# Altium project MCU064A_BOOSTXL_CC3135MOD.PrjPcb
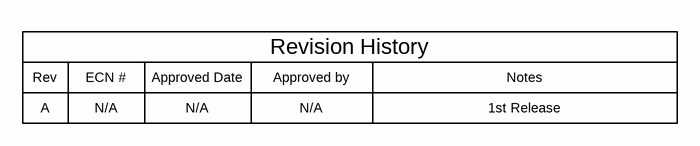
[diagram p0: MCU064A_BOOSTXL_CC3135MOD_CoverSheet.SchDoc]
CopyrightYear: 2016; EVM_Orderable: BOOSTXL-CC3135MOD; PCB_Layout: PMovva; PCB_Rev: A; PRJ_Customer: Public Release; PRJ_Engineer: PMovva; PRJ_Number: MCU064; PRJ_Title: BOOSTXL-CC3135MOD; SCH_Rev: A; TechSupport: http://www.ti.com/support; TID: N/A
4 sheets, 113 parts. Net scope: global (net labels, ports and power ports of the same name join across sheets).
Board file: MCU064A_BOOSTXL_CC3135MOD_PCB.PcbDoc
Sheets:
  MCU064A_BOOSTXL_CC3135MOD_CoverSheet.SchDoc
  MCU064A_BOOSTXL_CC3135MOD_Engine.SchDoc
  MCU064A_BOOSTXL_CC3135MOD_EVMHardware.SchDoc
  MCU064A_BOOSTXL_CC3135MOD_HostInterface.SchDoc

## Sheet MCU064A_BOOSTXL_CC3135MOD_CoverSheet.SchDoc: Cover
size 431 x 279 mm; Date: Not shown in title block; ApprovedBy: Not shown in title block; CheckedBy: Not shown in title block; Author: Not shown in title block; CompanyName: Not shown in title block; DrawnBy: PMovva; Engineer: Not shown in title block; Organization: Not shown in title block; Address1: Not shown in title block; Address2: Not shown in title block; Address3: Not shown in title block; Address4: Not shown in title block; DocumentNumber: 1; Revision: Use project parameter SCH_Rev; SheetNumber: 1; SheetTotal: 4; PageSetup: Record=PageOptions¦CenterHorizontal=True¦CenterVertical=True¦PrintScale=1.00¦XCorrection=1.00¦YCorrection=1.00¦PrintKind=0¦BorderSize=5000000¦LeftOffset=0¦BottomOffset=0¦Orientation=2¦PaperLength=1000¦PaperWidth=1000¦Scale=100¦PaperSource=15¦PrintQuality=600¦MediaType=1¦DitherType=10¦PaperKind=Letter¦PrintScaleMode=1

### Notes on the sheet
- Rev
- A
- ECN #
- N/A
- Approved Date
- Approved by
- Revision History
- Notes
- 1st Release

## Sheet MCU064A_BOOSTXL_CC3135MOD_Engine.SchDoc: Engine Area
size 558 x 431 mm; Date: Not shown in title block; ApprovedBy: Not shown in title block; CheckedBy: Not shown in title block; Author: Not shown in title block; CompanyName: Not shown in title block; DrawnBy: PMovva; Engineer: Not shown in title block; Organization: Not shown in title block; Address1: Not shown in title block; Address2: Not shown in title block; Address3: Not shown in title block; Address4: Not shown in title block; DocumentNumber: 2; Revision: Use project parameter SCH_Rev; SheetNumber: 2; SheetTotal: 4; PageSetup: Record=PageOptions¦CenterHorizontal=True¦CenterVertical=True¦PrintScale=1.00¦XCorrection=1.00¦YCorrection=1.00¦PrintKind=0¦BorderSize=5000000¦LeftOffset=0¦BottomOffset=0¦Orientation=2¦PaperLength=1000¦PaperWidth=1000¦Scale=100¦PaperSource=15¦PrintQuality=600¦MediaType=1¦DitherType=10¦PaperKind=Letter¦PrintScaleMode=1
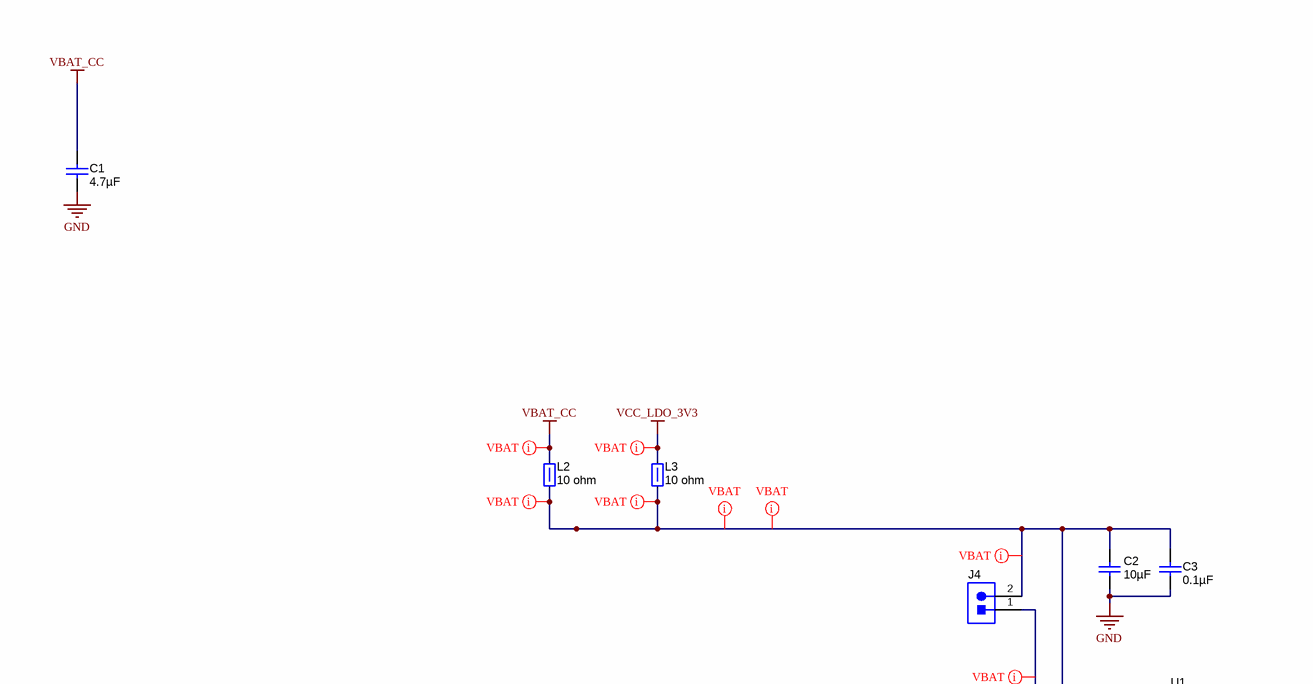
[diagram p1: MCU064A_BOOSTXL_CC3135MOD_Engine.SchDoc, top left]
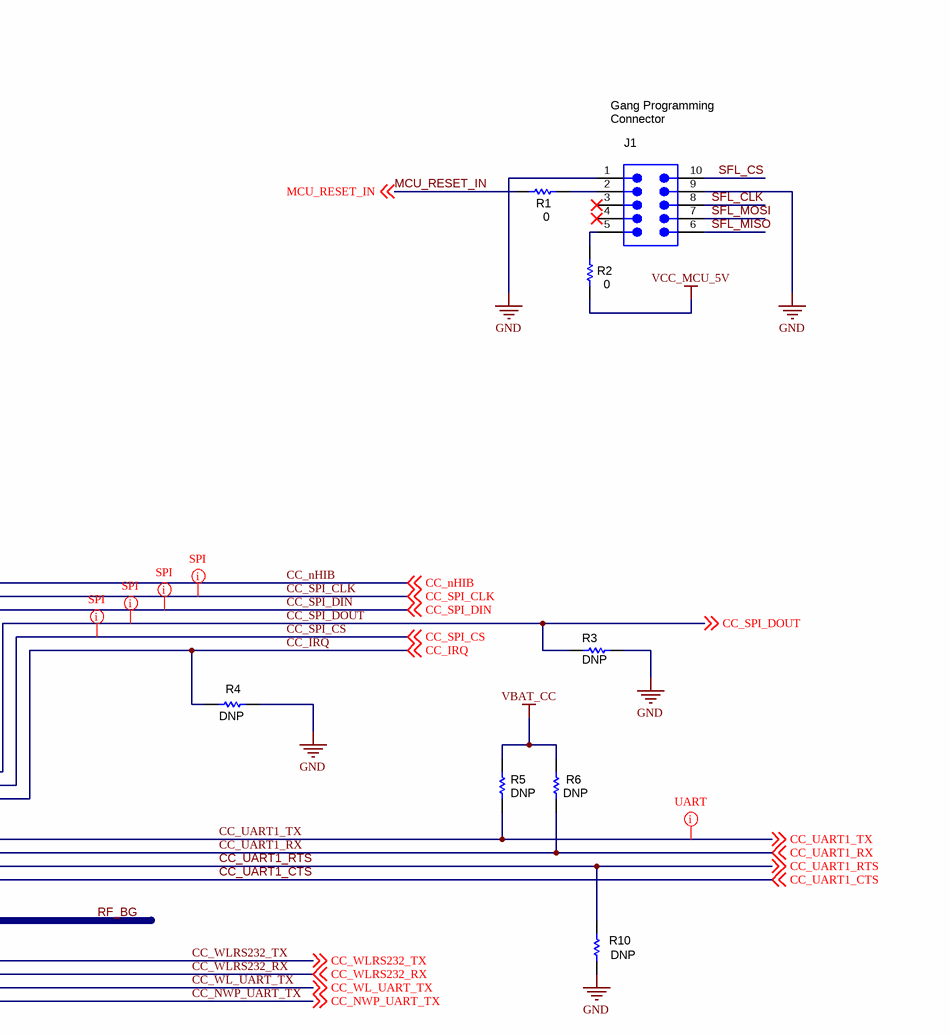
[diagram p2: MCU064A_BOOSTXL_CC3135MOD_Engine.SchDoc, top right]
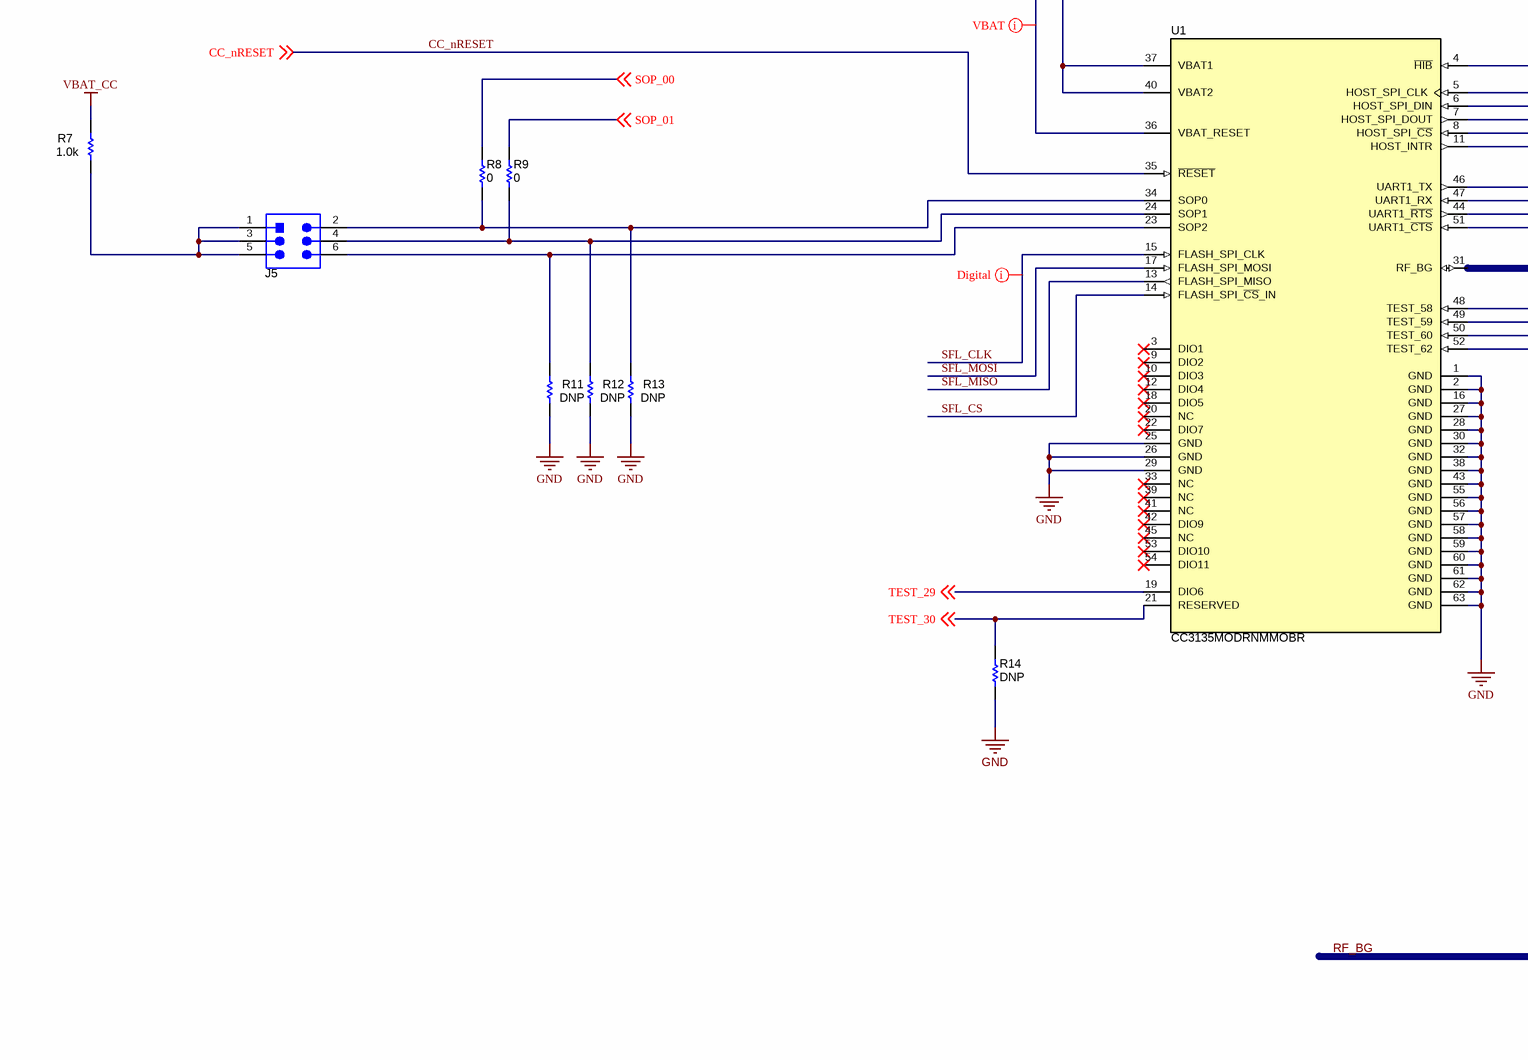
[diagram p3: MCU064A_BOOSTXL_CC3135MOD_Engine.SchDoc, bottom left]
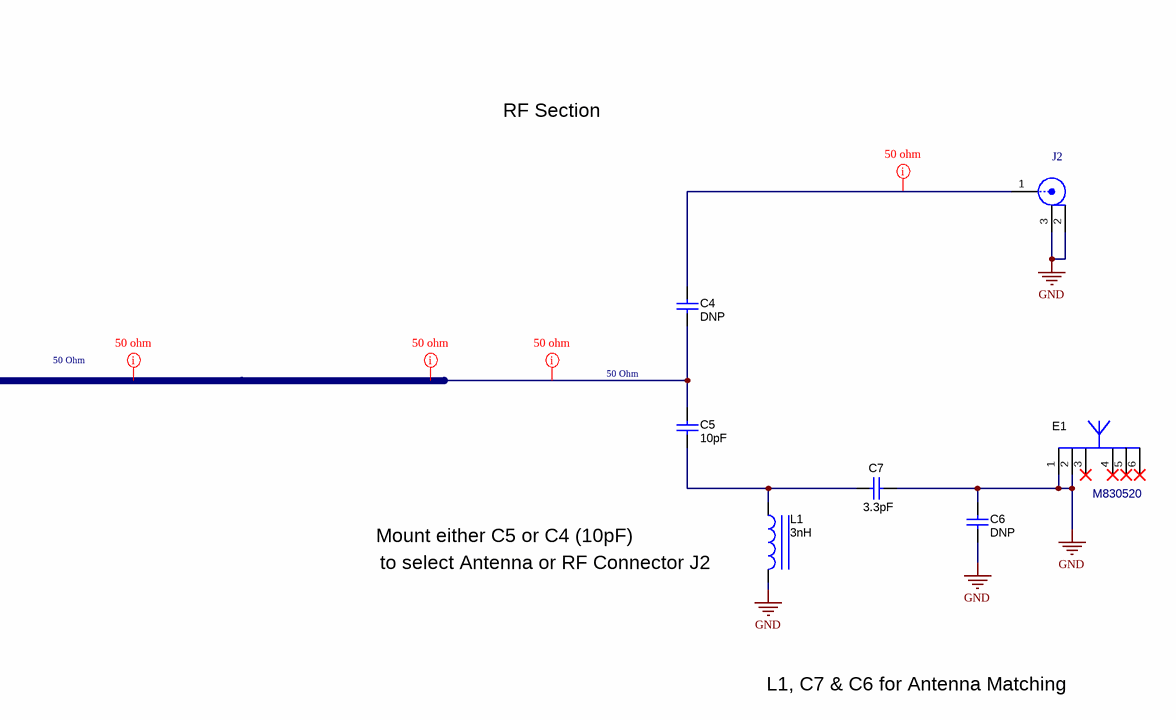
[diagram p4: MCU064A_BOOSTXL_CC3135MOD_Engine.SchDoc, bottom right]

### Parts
C1  ValueDisplayed: 4.7µF  [0402]  (hidden comment: GRM155R60J475ME47D)
C2  ValueDisplayed: 10µF  [0603]  (hidden comment: GRM188R60J106ME47D)
C3  ValueDisplayed: 0.1µF  [0402]  (hidden comment: GRM155R60J104KA01D)
C4  ValueDisplayed: DNP  [0402]  (hidden comment: 500R07S100JV4T)
C5  ValueDisplayed: 10pF  [0402]  (hidden comment: 500R07S100JV4T)
C6  ValueDisplayed: DNP  [0402]  (hidden comment: GRM1555C1H1R8CA01D)
C7  ValueDisplayed: 3.3pF  [0402]  (hidden comment: GJM1555C1H3R3BB01D)
E1  M830520  [Ethertronics_M830520]
J1  TC2050-IDC-430-FP  [Tag_TC2050-NL]  (value not drawn)  (no BOM)
J2  U.FL-R-SMT-1  [CONN_UFL-R-SMT-1]  (value not drawn)
J4  961102-6404-AR  [3M_961102-6404-AR]  (value not drawn)
J5  GRPB032VWVN-RC  [Sullins_GRPB032VWVN-RC]  (value not drawn)
L1  ValueDisplayed: 3nH  [IND_LQG15H]  (hidden comment: LQG15HS3N0S02D)
L2  value 10 ohm  [0402]  (hidden comment: BLM15AX100SN1D)
L3  value 10 ohm  [0402]  (hidden comment: BLM15AX100SN1D)
R1  ValueDisplayed: 0  [0402]  (hidden comment: ERJ-2GE0R00X)
R2  ValueDisplayed: 0  [0402]  (hidden comment: ERJ-2GE0R00X)
R3  ValueDisplayed: DNP  [0402]  (hidden comment: CRCW0402100KJNED)
R4  ValueDisplayed: DNP  [0402]  (hidden comment: CRCW0402100KJNED)
R5  ValueDisplayed: DNP  [0402]  (hidden comment: CRCW0402100KJNED)
R6  ValueDisplayed: DNP  [0402]  (hidden comment: CRCW0402100KJNED)
R7  ValueDisplayed: 1.0k  [0402]  (hidden comment: CRCW04021K00JNED)
R8  ValueDisplayed: 0  [0402]  (hidden comment: ERJ-2GE0R00X)
R9  ValueDisplayed: 0  [0402]  (hidden comment: ERJ-2GE0R00X)
R10  ValueDisplayed: DNP  [0402]  (hidden comment: CRCW0402100KJNED)
R11  ValueDisplayed: DNP  [0402]  (hidden comment: CRCW0402100KJNED)
R12  ValueDisplayed: DNP  [0402]  (hidden comment: CRCW0402100KJNED)
R13  ValueDisplayed: DNP  [0402]  (hidden comment: CRCW0402100KJNED)
R14  ValueDisplayed: DNP  [0402]  (hidden comment: CRCW0402100KJNED)
U1  CC3135MODRNMMOBR  [MOB0063A]

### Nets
GND: C1.2 C2.2 C3.2 C6.1 C6.2 C7.1 E1.1(Feed) E1.2(GND) J1.1 J1.9 J2.2 J2.3 L1.2 R3.2 R4.2 R10.2 R11.2 R12.2 R13.2 R14.1 U1.1(GND) U1.2(GND) U1.16(GND) U1.25(GND) U1.26(GND) U1.27(GND) U1.28(GND) U1.29(GND) U1.30(GND) U1.32(GND) U1.38(GND) U1.43(GND) U1.55(GND) U1.56(GND) U1.57(GND) U1.58(GND) U1.59(GND) U1.60(GND) U1.61(GND) U1.62(GND) U1.63(GND)
VBAT_CC: C1.1 L2.2 R5.1 R6.1 R7.1
VCC_LDO_3V3: L3.2
VCC_MCU_5V: R2.1
CC_IRQ: R4.1 U1.11(HOST_INTR) ; off-sheet CC_IRQ
CC_nHIB: U1.4(~{HIB}) ; off-sheet CC_nHIB
CC_nRESET: U1.35(~{RESET}) ; off-sheet CC_nRESET
CC_NWP_UART_TX: U1.52(TEST_62) ; off-sheet CC_NWP_UART_TX
CC_SPI_CLK: U1.5(HOST_SPI_CLK) ; off-sheet CC_SPI_CLK
CC_SPI_CS: U1.8(HOST_SPI_~{CS}) ; off-sheet CC_SPI_CS
CC_SPI_DIN: U1.6(HOST_SPI_DIN) ; off-sheet CC_SPI_DIN
CC_SPI_DOUT: R3.1 U1.7(HOST_SPI_DOUT) ; off-sheet CC_SPI_DOUT
CC_UART1_CTS: U1.51(UART1_~{CTS}) ; off-sheet CC_UART1_CTS
CC_UART1_RTS: R10.1 U1.44(UART1_~{RTS}) ; off-sheet CC_UART1_RTS
CC_UART1_RX: R6.2 U1.47(UART1_RX) ; off-sheet CC_UART1_RX
CC_UART1_TX: R5.2 U1.46(UART1_TX) ; off-sheet CC_UART1_TX
CC_WL_UART_TX: U1.50(TEST_60) ; off-sheet CC_WL_UART_TX
CC_WLRS232_RX: U1.49(TEST_59) ; off-sheet CC_WLRS232_RX
CC_WLRS232_TX: U1.48(TEST_58) ; off-sheet CC_WLRS232_TX
MCU_RESET_IN: R1.2 ; off-sheet MCU_RESET_IN
RF_BG: C4.2 C5.1 U1.31(RF_BG)
SFL_CLK: J1.8 U1.15(FLASH_SPI_CLK)
SFL_CS: J1.10 U1.14(FLASH_SPI_~{CS}_IN)
SFL_MISO: J1.6 U1.13(FLASH_SPI_MISO)
SFL_MOSI: J1.7 U1.17(FLASH_SPI_MOSI)
SOP_00: R8.2 ; off-sheet SOP_00
SOP_01: R9.2 ; off-sheet SOP_01
TEST_29: U1.19(DIO6) ; off-sheet TEST_29
TEST_30: R14.2 U1.21(RESERVED) ; off-sheet TEST_30
NetC2_1: C2.1 C3.1 J4.2 L2.1 L3.1 U1.37(VBAT1) U1.40(VBAT2)
NetC4_1: C4.1 J2.1
NetC5_2: C5.2 C7.2 L1.1
NetJ1_2: J1.2 R1.1
NetJ1_5: J1.5 R2.2
NetJ4_1: J4.1 U1.36(VBAT_RESET)
NetJ5_1: J5.1 J5.3 J5.5 R7.2
NetJ5_2: J5.2 R8.1 R13.1 U1.34(SOP0)
NetJ5_4: J5.4 R9.1 R12.1 U1.24(SOP1)
NetJ5_6: J5.6 R11.1 U1.23(SOP2)

Not connected (* = marked no-connect by the designer): E1 3(GND)* 4(Feed)* 5* 6*; J1 3* 4*; U1 3(DIO1)* 9(DIO2)* 10(DIO3)* 12(DIO4)* 18(DIO5)* 20(NC)* 22(DIO7)* 33(NC)* 39(NC)* 41(NC)* 42(DIO9)* 45(NC)* 53(DIO10)* 54(DIO11)*

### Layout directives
net class 50 ohm: NetC4_1, RF_BG
net class Undefined: CC_SPI_CLK, CC_SPI_CS, CC_SPI_DIN, CC_SPI_DOUT, CC_UART1_TX, NetC2_1, NetJ4_1, SFL_CLK, VBAT_CC, VCC_LDO_3V3
rule Undefined: NetC2_1

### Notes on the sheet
- Gang Programming
  Connector
- RF Section
- 50 Ohm
- Mount either C5 or C4 (10pF)
- (near L1) to select Antenna or RF Connector J2
- L1, C7 & C6 for Antenna Matching

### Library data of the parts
C1 = GRM155R60J475ME47D: CAP, CERM, 4.7 µF, 6.3 V, +/- 20%, X5R, 0402; Manufacturer: MuRata; Polarized: N; CompType: Capacitor; Value: 4.7uF; U/M: EA; Cap_F: 0.0000047; Tolerance_%: 20; Value1: Unknown; VDC_V: 6.3; Value2: 6.3V; TaMin_C: -55; TaMax_C: 85; SizeArea_mm2: 0.5; SizeAreaWB_mm2: 3; SizeX_mm: 1; SizeZ_mm: 0.6; AEC Category: Q200
C2 = GRM188R60J106ME47D: CAP, CERM, 10 µF, 6.3 V, +/- 20%, X5R, 0603; Manufacturer: MuRata; Polarized: N; CompType: Capacitor; Value: 10uF; U/M: EA; Cap_F: 0.00001; Tolerance_%: 20; ESR_ohm: 0.009; Value1: 0.009 ohm; VDC_V: 6.3; Value2: 6.3V; IRMS_A: 2.74; TaMin_C: -55; TaMax_C: 125; SizeArea_mm2: 1.28; SizeAreaWB_mm2: 4.68; SizeX_mm: 1.6; SizeY_mm: 0.8; SizeZ_mm: 1; AEC Category: Q200
C3 = GRM155R60J104KA01D: CAP, CERM, 0.1 µF, 6.3 V, +/- 10%, X5R, 0402; Manufacturer: MuRata; Polarized: N; CompType: Capacitor; Value: 0.1uF; U/M: EA; Cap_F: 0.0000001; Tolerance_%: 10; Value1: Unknown; VDC_V: 6.3; Value2: 6.3V; TaMin_C: -55; TaMax_C: 85; SizeArea_mm2: 0.5; SizeAreaWB_mm2: 3; SizeX_mm: 1; SizeZ_mm: 0.6; AEC Category: Q200
C4 C5 = 500R07S100JV4T: CAP, CERM, 10 pF, 50 V, +/- 5%, C0G/NP0, 0402; Manufacturer: Johanson Technology; Polarized: N; CompType: Capacitor; Value: 10pF; U/M: EA; Cap_F: 0.00000000001; Tolerance_%: 5; Value1: Unknown; VDC_V: 50; Value2: 50V; TaMin_C: -55; TaMax_C: 125; SizeArea_mm2: 0.5; SizeAreaWB_mm2: 3; SizeX_mm: 1; SizeZ_mm: 0.6; AEC Category: Q200
C6 = GRM1555C1H1R8CA01D: CAP, CERM, 1.8 pF, 50 V, +/- 5%, C0G/NP0, 0402; Manufacturer: MuRata; Polarized: N; CompType: Capacitor; Value: 1.8pF; U/M: EA; Cap_F: 0.0000000000018; Tolerance_%: 5; Value1: Unknown; VDC_V: 50; Value2: 50V; TaMin_C: -55; TaMax_C: 125; SizeArea_mm2: 0.5; SizeAreaWB_mm2: 3; SizeX_mm: 1; SizeZ_mm: 0.6; AEC Category: Q200
C7 = CMP-0006462-1: CAP, CERM, 3.3 pF, 50 V, +/- 0.1pF, C0G/NP0, 0402; Manufacturer: MuRata; TaMin_C: -55°C; Polarized: N; SizeAreaWB_mm2: 3; Value1: Unknown; U/M: EA; Value: 3.3pF; TaMax_C: 125°C; SizeZ_mm: 0.6; SizeX_mm: 1; SizeY_mm: 0.5; Value2: 50V; AEC Category: Q200
E1 = CMP-0001857-1: WLAN ANTENNA 802.11, SMD; Manufacturer: Ethertronics; SizeZ_mm: 1.33; SizeX_mm: 3; SizeY_mm: 8; SizeAreaWB_mm2: 50; SizeArea_mm2: 24
J1 = TC2050-IDC-430-FP: Footprint for TC2050-IDC-430; Manufacturer: Tag-Connect; SymbolCreator: a0799628; CompType: Receptacle; U/M: EA; Note: Footprint only, to mate with Tag-Connect cable P/N TC2050-IDC-430
J2 = U.FL-R-SMT-1: Connector, Ultra-Mini Coaxial, SMD; Manufacturer: Hirose Electric Co. Ltd.; SymbolCreator: a0412235; U/M: EA
J4 = 961102-6404-AR: Header, 2.54mm, 2x1, TH; Manufacturer: 3M; SymbolCreator: a0412235; Pitch_mm: 2.54; Gender: Male; Shrouded: N; Row_Count: 1; ContactFinish: Gold; Current_A: 2; Voltage_V: 1000; Cert_UL: Y
J5 = GRPB032VWVN-RC: Header, 50mil, 3x2, Gold, TH; Manufacturer: Sullins Connector Solutions; SymbolCreator: a0412235
L1 = CMP-0058630-1: Inductor, Multilayer, Air Core, 3 nH, 0.3 A, 0.17 ohm, SMD; Manufacturer: MuRata; Isat: 0.3A @ % inductance drop; Irms: 0.3A @ C rise; Green_Lifecycle: Active; SizeAreaWB_mm2: 3; DCR_ohm: 0.17; Green_REACh: Passed; Value: 3nH; Imax_A: 300mA; SizeZ_mm: 0.55; SizeX_mm: 1; SizeY_mm: 0.5; Value2: 0.3A; AEC Category: Q200
L2 L3 = BLM15AX100SN1D: Ferrite Bead, 10 ohm @ 100 MHz, 1.74 A, 0402; Manufacturer: MuRata; Imax_A: 1.74; DCR_ohm: 0.015; Value1: 0.015 ohm; Value2: 1.74A; ZTyp@100MHz_Ohm: 10; SizeAreaWB_mm2: 3; SizeArea_mm2: 0.5; SizeX_mm: 1; SizeZ_mm: 0.6
R1 R2 R8 R9 = ERJ-2GE0R00X: RES, 0, 5%, 0.063 W, 0402; Manufacturer: Panasonic; CompType: Resistor; Value: 0; Value_Code: 0000; Tolerance_%: 5; Power_W: 0.063; Value2: 0.063W; VDC_V: 50; TempCo: 600 ppm/C; EIA_Code: E24; U/M: EA; SizeArea_mm2: 0.5; SizeX_mm: 1; SizeZ_mm: 0.6; AEC Category: Q200
R3-R6 R10-R14 = CRCW0402100KJNED: RES, 100 k, 5%, 0.063 W, 0402; Manufacturer: Vishay-Dale; CompType: Resistor; Value: 100k; Res_ohm: 100000; Tolerance_%: 5; Power_W: 0.063; Value2: 0.063W; VDC_V: 50; TempCo: 200 ppm/C; EIA_Code: E24; U/M: EA; SizeArea_mm2: 0.5; SizeX_mm: 1; SizeZ_mm: 0.6; AEC Category: Q200
R7 = CRCW04021K00JNED: RES, 1.0 k, 5%, 0.063 W, 0402; Manufacturer: Vishay-Dale; CompType: Resistor; Value: 1.0k; Res_ohm: 1000; Value_Code: 1k00; Tolerance_%: 5; Power_W: 0.063; Value2: 0.063W; VDC_V: 50; TempCo: 200 ppm/C; EIA_Code: E24; U/M: EA; SizeArea_mm2: 0.5; SizeX_mm: 1; SizeZ_mm: 0.6; AEC Category: Q200
U1 = CC3120MODRNMMOBR: SimpleLink Certified Wi-Fi Network Processor Internet-of-Things Module Solution for MCU Applications, MOB0063A (QFM-63); Manufacturer: Texas Instruments; SymbolCreator: Altium; SizeArea_mm2: 358.75; SizeAreaWB_mm2: 438.75; SizeX_mm: 17.5; SizeY_mm: 20.5; SizeZ_mm: 2.45; CompType: IC; U/M: EA

## Sheet MCU064A_BOOSTXL_CC3135MOD_EVMHardware.SchDoc: EVM Hardware
size 431 x 279 mm; Date: Not shown in title block; ApprovedBy: Not shown in title block; CheckedBy: Not shown in title block; Author: Not shown in title block; CompanyName: Not shown in title block; DrawnBy: Eric Greenstein; Engineer: Not shown in title block; Organization: Not shown in title block; Address1: Not shown in title block; Address2: Not shown in title block; Address3: Not shown in title block; Address4: Not shown in title block; DocumentNumber: 4; Revision: Use project parameter SCH_Rev; SheetNumber: 4; SheetTotal: 4; PageSetup: Record=PageOptions¦CenterHorizontal=True¦CenterVertical=True¦PrintScale=1.00¦XCorrection=1.00¦YCorrection=1.00¦PrintKind=0¦BorderSize=5000000¦LeftOffset=0¦BottomOffset=0¦Orientation=2¦PaperLength=1000¦PaperWidth=1000¦Scale=100¦PaperSource=15¦PrintQuality=600¦MediaType=1¦DitherType=10¦PaperKind=Letter¦PrintScaleMode=1
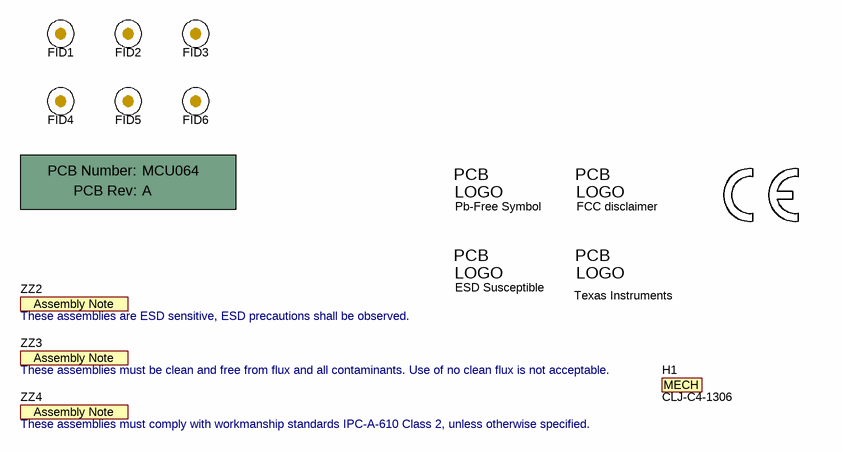
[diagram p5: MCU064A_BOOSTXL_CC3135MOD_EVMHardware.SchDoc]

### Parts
!PCB  Printed Circuit Board  (value not drawn)  (mechanical)
FID1  Fiducial  [Fiducial6.4-20]  (value not drawn)
FID2  Fiducial  [Fiducial6.4-20]  (value not drawn)
FID3  Fiducial  [Fiducial6.4-20]  (value not drawn)
FID4  Fiducial  [Fiducial6.4-20]  (value not drawn)
FID5  Fiducial  [Fiducial6.4-20]  (value not drawn)
FID6  Fiducial  [Fiducial6.4-20]  (value not drawn)
H1  CLJ-C4-1306  (mechanical)
Logo1  Texas Instruments  [TI_Symbol_Overlay_Small]  (no BOM)
Logo2  Pb-Free Symbol  [Pb-Free_Overlay_Small]  (no BOM)
Logo3  FCC disclaimer  [FCC_disclaimer]  (no BOM)
LOGO4  CE Mark  [CE_Mark_5mm]  (value not drawn)  (no BOM)
Logo5  ESD Susceptible  [ESD_Overlay_Small]  (no BOM)
ZZ2  These assemblies are ESD sensitive, ESD precautions shall be observed.  [AssemblyNote]  (no BOM)
ZZ3  These assemblies must be clean and free from flux and all contaminants. Use of no clean flux is not acceptable.  [AssemblyNote]  (no BOM)
ZZ4  These assemblies must comply with workmanship standards IPC-A-610 Class 2, unless otherwise specified.  [AssemblyNote]  (no BOM)

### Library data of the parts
!PCB = PCB: Manufacturer: Any; PartNumber: MCU064; SymbolCreator: a0412235
FID1-FID6 = Fiducial: Fiducial mark.  There is nothing to buy or mount.; SymbolCreator: codlsc
H1 = MechPart: Will add component to BOM.  Useful for cables, nuts, etc. not in libraries; Manufacturer: Used in BOM report; SymbolCreator: codlsc; CompType: Mechanical; U/M: EA
Logo1 = TI_Logo: Texas Instrument Corporate Signature; SymbolCreator: a0412235
Logo2 = Pb-Free: SymbolCreator: a0412235
Logo3 = FCC_disclaimer: SymbolCreator: a0412235
LOGO4 = CE Mark: SymbolCreator: a0412235
Logo5 = ESD_Susceptible: ESD Susceptible Symbol; SymbolCreator: a0412235
ZZ2 = CMP-0077236-1
ZZ3 = CMP-0077237-1
ZZ4 = CMP-0077238-1

## Sheet MCU064A_BOOSTXL_CC3135MOD_HostInterface.SchDoc: Host Interface
size 558 x 431 mm; Date: Not shown in title block; ApprovedBy: Not shown in title block; CheckedBy: Not shown in title block; Author: Not shown in title block; CompanyName: Not shown in title block; DrawnBy: Eric Greenstein; Engineer: Not shown in title block; Organization: Not shown in title block; Address1: Not shown in title block; Address2: Not shown in title block; Address3: Not shown in title block; Address4: Not shown in title block; DocumentNumber: 3; Revision: Use project parameter SCH_Rev; SheetNumber: 3; SheetTotal: 4; PageSetup: Record=PageOptions¦CenterHorizontal=True¦CenterVertical=True¦PrintScale=1.00¦XCorrection=1.00¦YCorrection=1.00¦PrintKind=0¦BorderSize=5000000¦LeftOffset=0¦BottomOffset=0¦Orientation=2¦PaperLength=1000¦PaperWidth=1000¦Scale=100¦PaperSource=15¦PrintQuality=600¦MediaType=1¦DitherType=10¦PaperKind=Letter¦PrintScaleMode=1
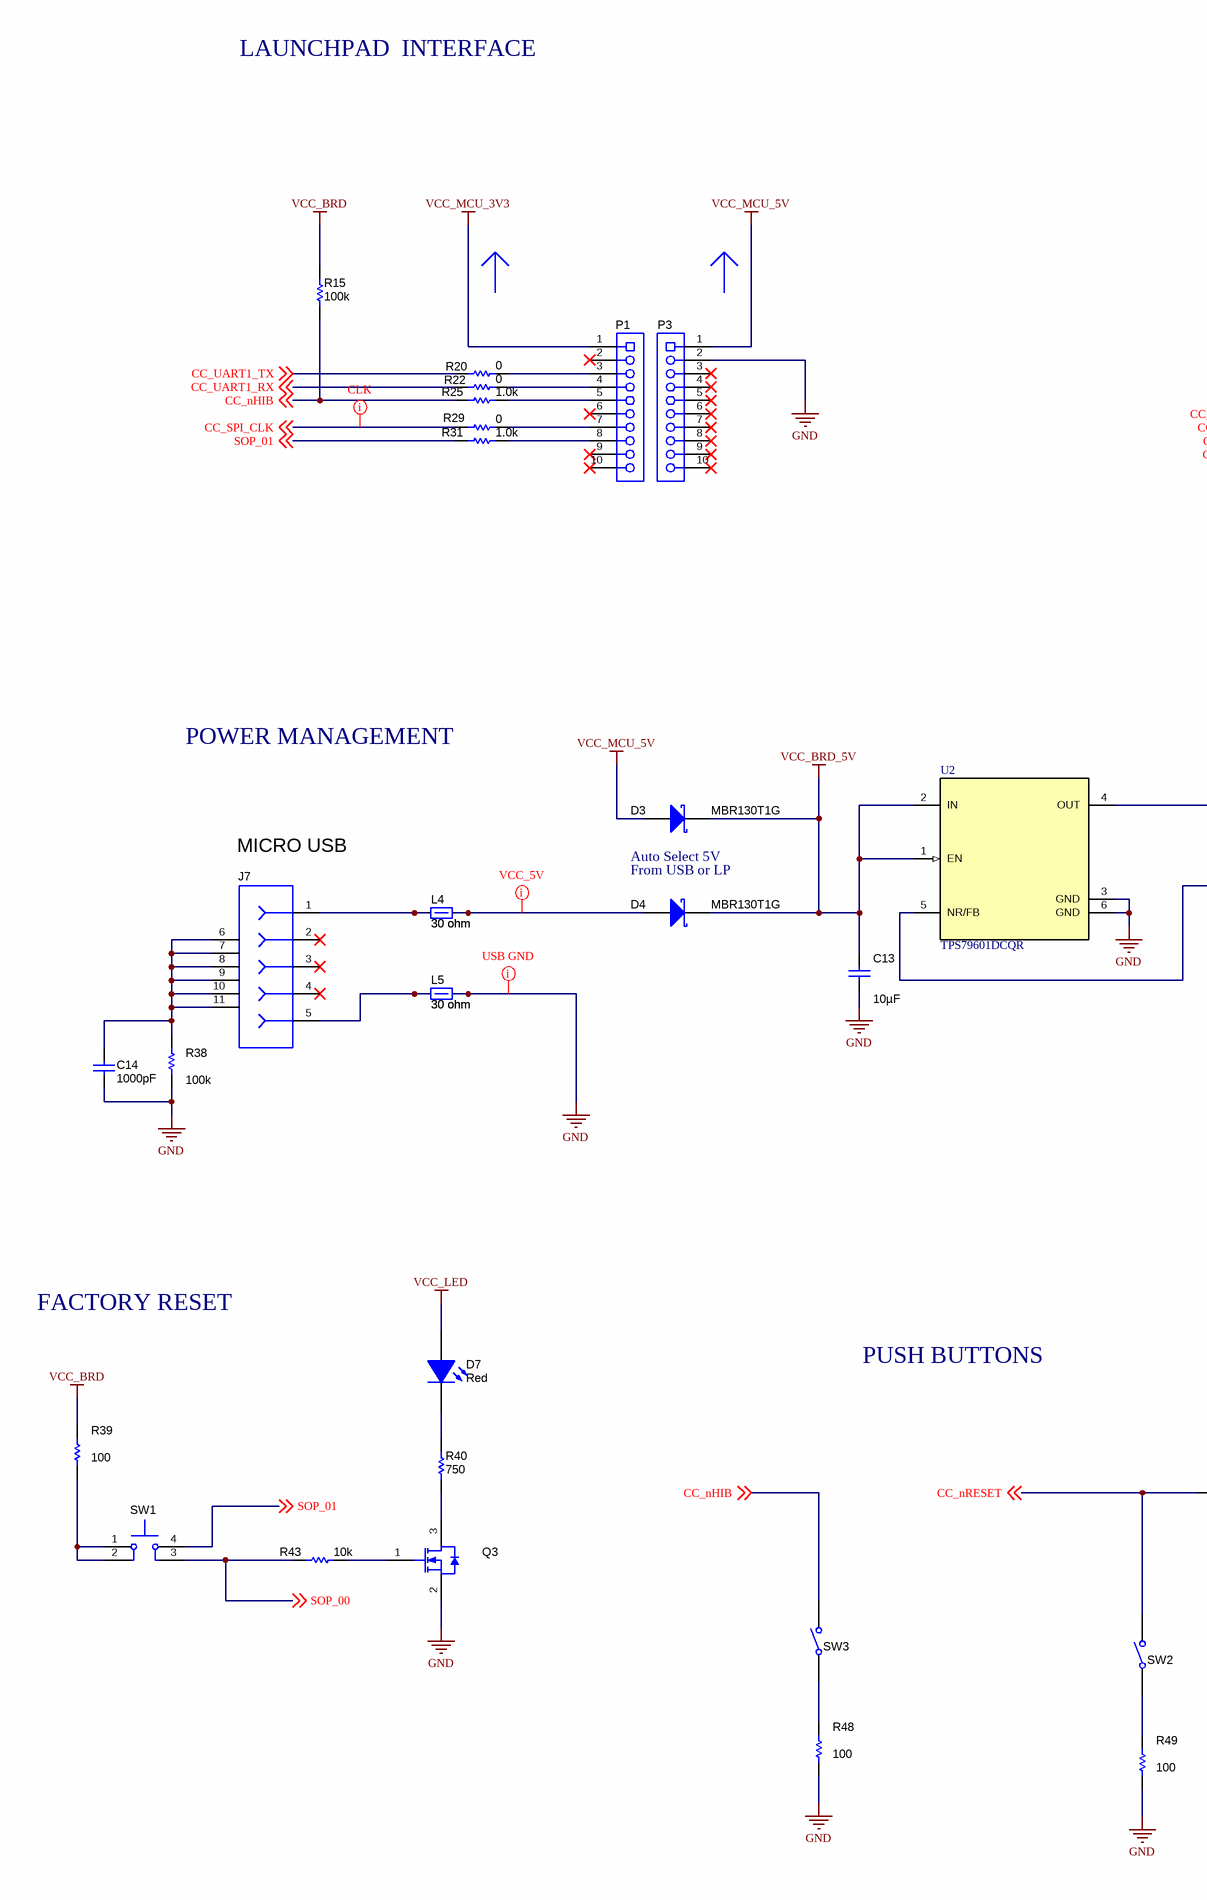
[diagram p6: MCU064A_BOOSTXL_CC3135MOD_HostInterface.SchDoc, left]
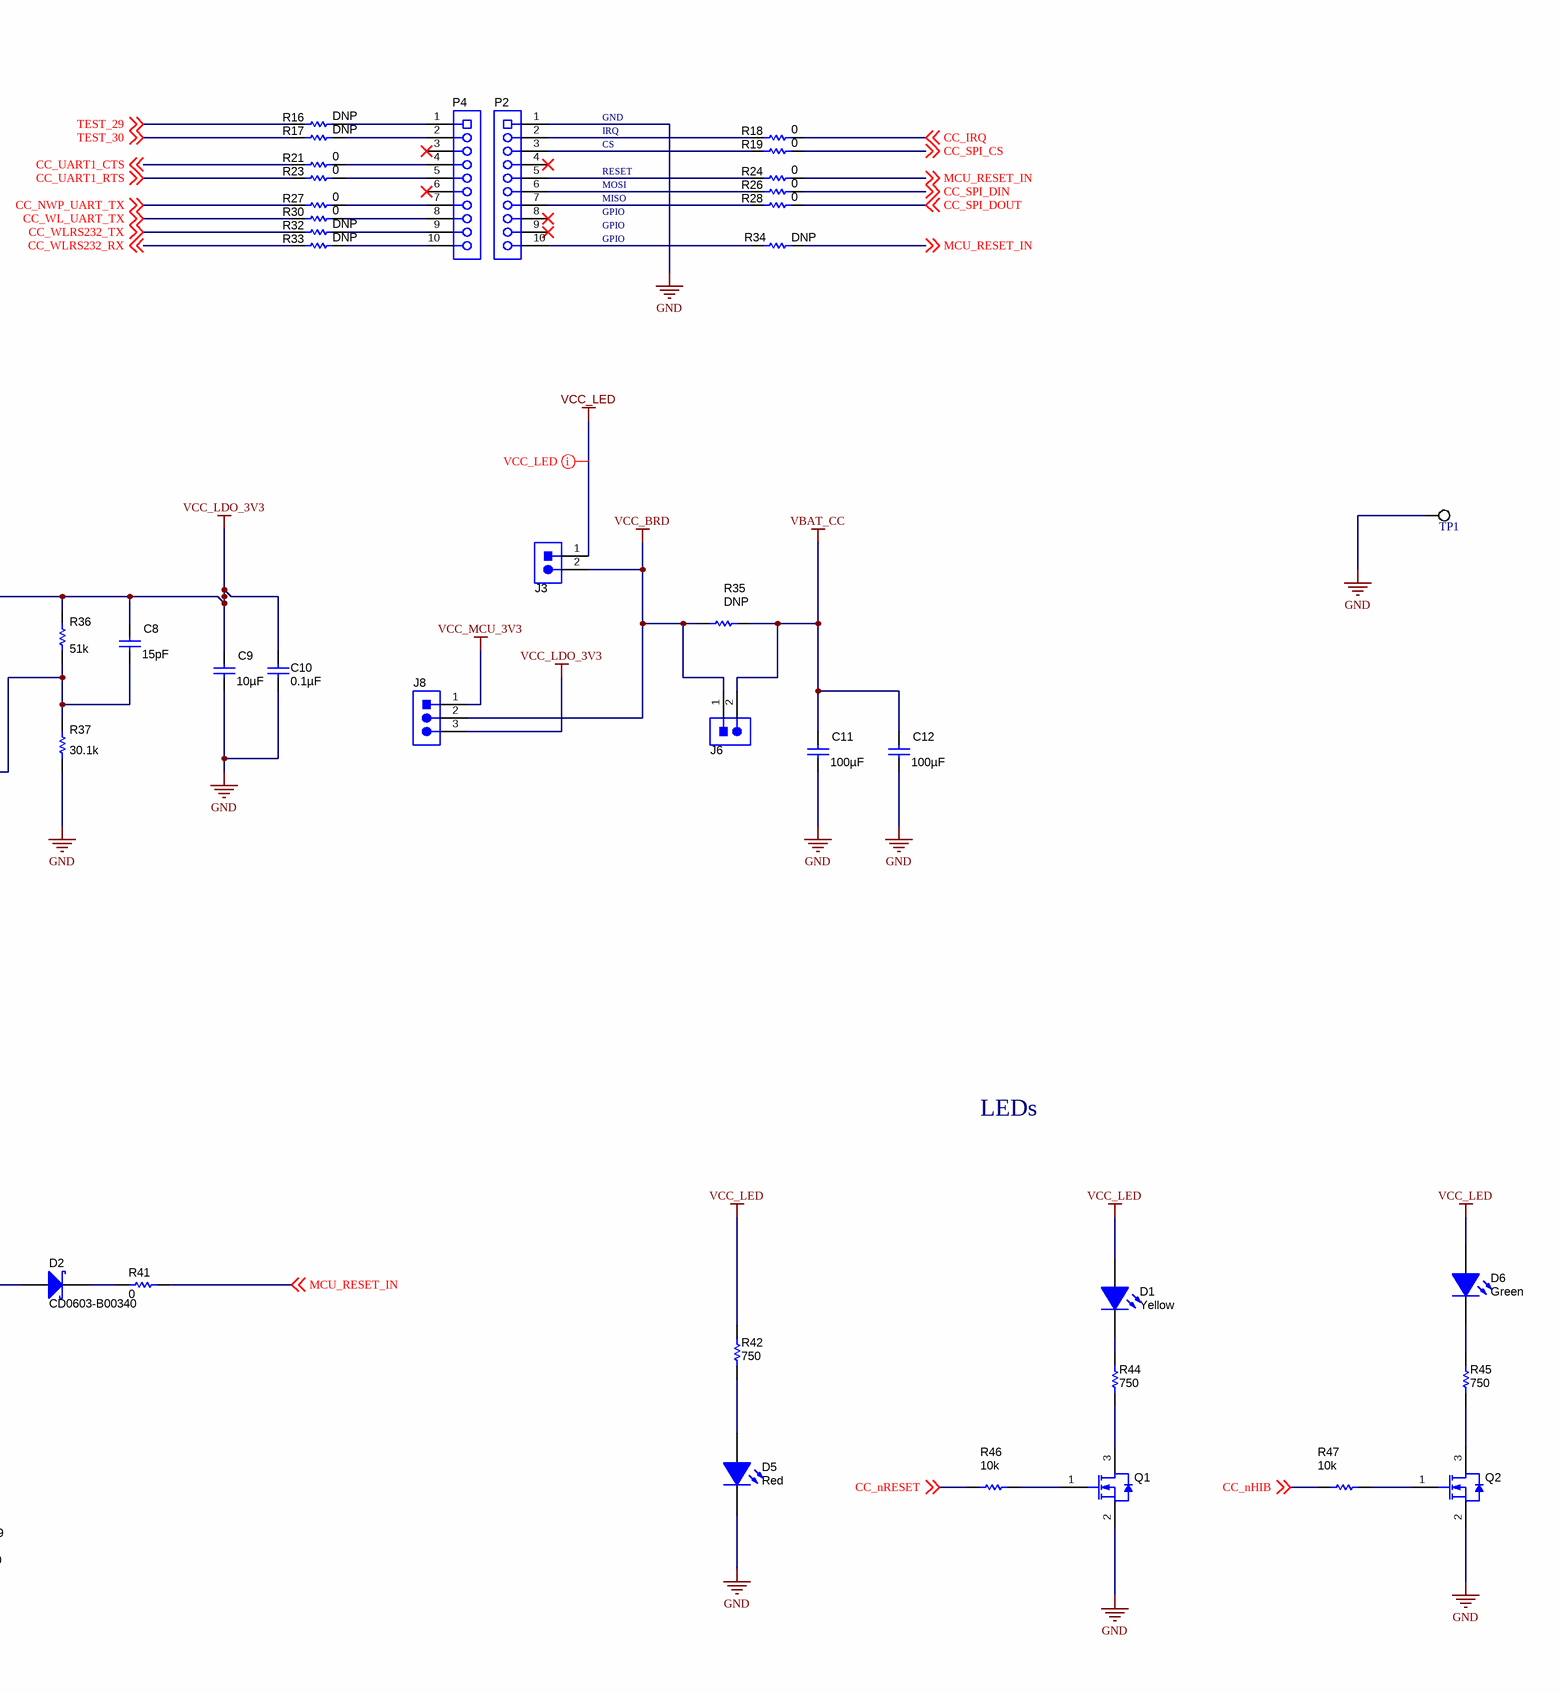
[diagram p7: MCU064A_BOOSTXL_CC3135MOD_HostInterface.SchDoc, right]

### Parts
C8  ValueDisplayed: 15pF  [0402]  (hidden comment: GRM1555C1H150JA01D)
C9  ValueDisplayed: 10µF  [0805_HV]  (hidden comment: GRM21BR61A106KE19L)
C10  ValueDisplayed: 0.1µF  [0402]  (hidden comment: GRM155R60J104KA01D)
C11  ValueDisplayed: 100µF  [1206_180]  (hidden comment: GRM31CR60J107ME39L)
C12  ValueDisplayed: 100µF  [1206_180]  (hidden comment: GRM31CR60J107ME39L)
C13  ValueDisplayed: 10µF  [0805_HV]  (hidden comment: GRM21BR61A106KE19L)
C14  ValueDisplayed: 1000pF  [0402]  (hidden comment: GRM155R71H102KA01D)
D1  value Yellow  [WL-SMCW_YELLOW]  (hidden comment: 150060YS75000)
D2  CD0603-B00340  [Diode_0603]
D3  MBR130T1G  [SOD-123]
D4  MBR130T1G  [SOD-123]
D5  value Red  [SML-31_Red]  (hidden comment: SML-311UTT86)
D6  value Green  [WL-SMCW_GREEN]  (hidden comment: 150060GS75000)
D7  value Red  [WL-SMCW_RED]  (hidden comment: 150060RS75000)
J3  HMTSW-102-07-G-S-240  [SAMTEC_HMTSW-102-07-G-S-240]  (value not drawn)
J6  HMTSW-102-07-G-S-240  [SAMTEC_HMTSW-102-07-G-S-240]  (value not drawn)
J7  105017-0001  [CONN_105017-0001]  (value not drawn)
J8  TSW-103-07-G-S  [TSW-103-07-G-S]  (value not drawn)
L4  value 30 ohm  [0805_HV]  (hidden comment: MMZ2012R300A)
L5  value 30 ohm  [0805_HV]  (hidden comment: MMZ2012R300A)
P1  SSW-110-23-F-S  [CONN_SSW-110-23-F-S]  (value not drawn)
P2  SSW-110-23-F-S  [CONN_SSW-110-23-F-S]  (value not drawn)
P3  SSW-110-23-F-S  [CONN_SSW-110-23-F-S]  (value not drawn)
P4  SSW-110-23-F-S  [CONN_SSW-110-23-F-S]  (value not drawn)
Q1  BSS138  [SOT-23]  (value not drawn)
Q2  BSS138  [SOT-23]  (value not drawn)
Q3  BSS138  [SOT-23]  (value not drawn)
R15  ValueDisplayed: 100k  [0402]  (hidden comment: CRCW0402100KFKED)
R16  ValueDisplayed: DNP  [0402]  (hidden comment: ERJ-2GE0R00X)
R17  ValueDisplayed: DNP  [0402]  (hidden comment: ERJ-2GE0R00X)
R18  ValueDisplayed: 0  [0402]  (hidden comment: ERJ-2GE0R00X)
R19  ValueDisplayed: 0  [0402]  (hidden comment: ERJ-2GE0R00X)
R20  ValueDisplayed: 0  [0402]  (hidden comment: ERJ-2GE0R00X)
R21  ValueDisplayed: 0  [0402]  (hidden comment: ERJ-2GE0R00X)
R22  ValueDisplayed: 0  [0402]  (hidden comment: ERJ-2GE0R00X)
R23  ValueDisplayed: 0  [0402]  (hidden comment: ERJ-2GE0R00X)
R24  ValueDisplayed: 0  [0402]  (hidden comment: ERJ-2GE0R00X)
R25  ValueDisplayed: 1.0k  [0402]  (hidden comment: CRCW04021K00JNED)
R26  ValueDisplayed: 0  [0402]  (hidden comment: ERJ-2GE0R00X)
R27  ValueDisplayed: 0  [0402]  (hidden comment: ERJ-2GE0R00X)
R28  ValueDisplayed: 0  [0402]  (hidden comment: ERJ-2GE0R00X)
R29  value 0  [0402]  (hidden comment: ERJ-2GE0R00X)
R30  ValueDisplayed: 0  [0402]  (hidden comment: ERJ-2GE0R00X)
R31  ValueDisplayed: 1.0k  [0402]  (hidden comment: CRCW04021K00JNED)
R32  ValueDisplayed: DNP  [0402]  (hidden comment: ERJ-2GE0R00X)
R33  ValueDisplayed: DNP  [0402]  (hidden comment: ERJ-2GE0R00X)
R34  ValueDisplayed: DNP  [0402]  (hidden comment: ERJ-2GE0R00X)
R35  ValueDisplayed: DNP  [0805_HV]  (hidden comment: CRM0805-FX-R100ELF)
R36  ValueDisplayed: 51k  [0402]  (hidden comment: CRCW040251K0JNED)
R37  ValueDisplayed: 30.1k  [0402]  (hidden comment: CRCW040230K1FKED)
R38  ValueDisplayed: 100k  [0402]  (hidden comment: CRCW0402100KJNED)
R39  ValueDisplayed: 100  [0402]  (hidden comment: ERJ-2RKF1000X)
R40  ValueDisplayed: 750  [0603]  (hidden comment: RC0603JR-07750RL)
R41  ValueDisplayed: 0  [0402]  (hidden comment: ERJ-2GE0R00X)
R42  ValueDisplayed: 750  [0603]  (hidden comment: RC0603JR-07750RL)
R43  ValueDisplayed: 10k  [0402]  (hidden comment: CRCW040210K0JNED)
R44  ValueDisplayed: 750  [0603]  (hidden comment: RC0603JR-07750RL)
R45  ValueDisplayed: 750  [0603]  (hidden comment: RC0603JR-07750RL)
R46  ValueDisplayed: 10k  [0402]  (hidden comment: CRCW040210K0JNED)
R47  ValueDisplayed: 10k  [0402]  (hidden comment: CRCW040210K0JNED)
R48  ValueDisplayed: 100  [0402]  (hidden comment: ERJ-2RKF1000X)
R49  ValueDisplayed: 100  [0402]  (hidden comment: ERJ-2RKF1000X)
SW1  EVQ-PSD02K  [SW_EVQ-PSD02K]  (value not drawn)
SW2  MJTP1117  [SW_MJTP1117]  (value not drawn)
SW3  MJTP1117  [SW_MJTP1117]  (value not drawn)
TP1  5015  [Testpoint_Keystone_Miniature]  (value not drawn)
U2  TPS79601DCQR  [DCQ0006A]

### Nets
GND: C9.2 C10.2 C11.2 C12.2 C13.2 C14.2 D5.1(K) L5.1 P2.1 P3.2 Q1.2(S) Q2.2(S) Q3.2(S) R37.1 R38.2 R48.1 R49.1 TP1.1 U2.3(GND) U2.6(GND)
VBAT_CC: C11.1 C12.1 J6.2 R35.2
VCC_BRD: J3.2 J6.1 J8.2 R15.2 R35.1 R39.2
VCC_BRD_5V: C13.1 D3.1(K) D4.1(K) U2.1(EN) U2.2(IN)
VCC_LDO_3V3: C8.1 C9.1 C10.1 J8.3 R36.2 U2.4(OUT)
VCC_LED: D1.2(A) D6.2(A) D7.2(A) J3.1 R42.2
VCC_MCU_3V3: J8.1 P1.1
VCC_MCU_5V: D3.2(A) P3.1
CC_IRQ: R18.2 ; off-sheet CC_IRQ
CC_nHIB: R15.1 R25.1 R47.1 SW3.2 ; off-sheet CC_nHIB
CC_nRESET: D2.2(A) R46.1 SW2.2 ; off-sheet CC_nRESET
CC_NWP_UART_TX: R27.1 ; off-sheet CC_NWP_UART_TX
CC_SPI_CLK: R29.1 ; off-sheet CC_SPI_CLK
CC_SPI_CS: R19.2 ; off-sheet CC_SPI_CS
CC_SPI_DIN: R26.2 ; off-sheet CC_SPI_DIN
CC_SPI_DOUT: R28.2 ; off-sheet CC_SPI_DOUT
CC_UART1_CTS: R21.1 ; off-sheet CC_UART1_CTS
CC_UART1_RTS: R23.1 ; off-sheet CC_UART1_RTS
CC_UART1_RX: R22.1 ; off-sheet CC_UART1_RX
CC_UART1_TX: R20.1 ; off-sheet CC_UART1_TX
CC_WL_UART_TX: R30.1 ; off-sheet CC_WL_UART_TX
CC_WLRS232_RX: R33.1 ; off-sheet CC_WLRS232_RX
CC_WLRS232_TX: R32.1 ; off-sheet CC_WLRS232_TX
MCU_RESET_IN: R24.2 R34.2 R41.2 ; off-sheet MCU_RESET_IN
SOP_00: R43.1 SW1.3 ; off-sheet SOP_00
SOP_01: R31.1 SW1.4 ; off-sheet SOP_01
TEST_29: R16.1 ; off-sheet TEST_29
TEST_30: R17.1 ; off-sheet TEST_30
NetC8_2: C8.2 R36.1 R37.2 U2.5(NR/FB)
NetC14_1: C14.1 J7.6 J7.7 J7.8 J7.9 J7.10 J7.11 R38.1
NetD1_1: D1.1(K) R44.2
NetD2_1: D2.1(K) R41.1
NetD4_2: D4.2(A) L4.2
NetD5_2: D5.2(A) R42.1
NetD6_1: D6.1(K) R45.2
NetD7_1: D7.1(K) R40.2
NetJ7_1: J7.1 L4.1
NetJ7_5: J7.5 L5.2
NetP1_3: P1.3 R20.2
NetP1_4: P1.4 R22.2
NetP1_5: P1.5 R25.2
NetP1_7: P1.7 R29.2
NetP1_8: P1.8 R31.2
NetP2_2: P2.2 R18.1
NetP2_3: P2.3 R19.1
NetP2_5: P2.5 R24.1
NetP2_6: P2.6 R26.1
NetP2_7: P2.7 R28.1
NetP2_10: P2.10 R34.1
NetP4_1: P4.1 R16.2
NetP4_2: P4.2 R17.2
NetP4_4: P4.4 R21.2
NetP4_5: P4.5 R23.2
NetP4_7: P4.7 R27.2
NetP4_8: P4.8 R30.2
NetP4_9: P4.9 R32.2
NetP4_10: P4.10 R33.2
NetQ1_1: Q1.1(G) R46.2
NetQ1_3: Q1.3(D) R44.1
NetQ2_1: Q2.1(G) R47.2
NetQ2_3: Q2.3(D) R45.1
NetQ3_1: Q3.1(G) R43.2
NetQ3_3: Q3.3(D) R40.1
NetR39_1: R39.1 SW1.1 SW1.2
NetR48_2: R48.2 SW3.1
NetR49_2: R49.2 SW2.1

Not connected (* = marked no-connect by the designer): J7 2* 3* 4*; P1 2* 6* 9* 10*; P2 4* 8* 9*; P3 3* 4* 5* 6* 7* 8* 9* 10*; P4 3* 6*

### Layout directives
net class Undefined: CC_SPI_CLK, GND, NetD4_2, VCC_LED

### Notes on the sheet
- LAUNCHPAD  INTERFACE
- GND
- IRQ
- CS
- RESET
- MOSI
- MISO
- GPIO
- POWER MANAGEMENT
- MICRO USB
- Auto Select 5V
- From USB or LP
- FACTORY RESET
- LEDs
- PUSH BUTTONS

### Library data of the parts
C8 = GRM1555C1H150JA01D: CAP, CERM, 15 pF, 50 V, +/- 5%, C0G/NP0, 0402; Manufacturer: MuRata; Polarized: N; CompType: Capacitor; Value: 15pF; U/M: EA; Cap_F: 0.000000000015; Tolerance_%: 5; Value1: Unknown; VDC_V: 50; Value2: 50V; TaMin_C: -55; TaMax_C: 125; SizeArea_mm2: 0.5; SizeAreaWB_mm2: 3; SizeX_mm: 1; SizeZ_mm: 0.6; AEC Category: Q200
C9 C13 = GRM21BR61A106KE19L: CAP, CERM, 10 µF, 10 V, +/- 10%, X5R, 0805; Manufacturer: MuRata; Polarized: N; CompType: Capacitor; Value: 10uF; U/M: EA; Cap_F: 0.00001; Tolerance_%: 10; ESR_ohm: 0.002; Value1: 0.002 ohm; Value2: 10V; TaMin_C: -55; TaMax_C: 85; Cap_Case: 0805; SizeArea_mm2: 2.5; SizeAreaWB_mm2: 6.75; SizeX_mm: 2; SizeY_mm: 1.25; SizeZ_mm: 1.45; AEC Category: Q200
C10 = GRM155R60J104KA01D: as C3 on sheet MCU064A_BOOSTXL_CC3135MOD_Engine
C11 C12 = GRM31CR60J107ME39L: CAP, CERM, 100 µF, 6.3 V, +/- 20%, X5R, 1206; Manufacturer: MuRata; Polarized: N; CompType: Capacitor; Value: 100uF; U/M: EA; Cap_F: 0.0001; Tolerance_%: 20; ESR_ohm: 0.003; Value1: 0.003 ohm; VDC_V: 6.3; Value2: 6.3V; TaMin_C: -55; TaMax_C: 85; Cap_Case: 1206; SizeArea_mm2: 5.12; SizeAreaWB_mm2: 10.92; SizeX_mm: 3.2; SizeY_mm: 1.6; SizeZ_mm: 1.8; AEC Category: Q200
C14 = GRM155R71H102KA01D: CAP, CERM, 1000 pF, 50 V, +/- 10%, X7R, 0402; Manufacturer: MuRata; Polarized: N; CompType: Capacitor; Value: 1000pF; U/M: EA; Cap_F: 0.000000001; Tolerance_%: 10; Value1: Unknown; VDC_V: 50; Value2: 50V; TaMin_C: -55; TaMax_C: 125; SizeArea_mm2: 0.5; SizeAreaWB_mm2: 3; SizeX_mm: 1; SizeZ_mm: 0.6; AEC Category: Q200
D1 = 150060YS75000: LED, Yellow, SMD; Manufacturer: Wurth Elektronik; Type: AlInGaP; Vf_V: 2; Value2: 2V; Io_A: 0.02; Value1: W; U/M: EA
D2 = CD0603-B00340: Diode, Schottky, 45 V, 0.03 A, 0603 Diode; Manufacturer: Bourns; U/M: EA; Vf_V: 0.37; Value: 45V; Value1: 0.03A; Value2: 0.37V; Io_A: 0.03; Vr_V: 45; TJmax_C: 125; SizeAreaWB_mm2: 5.13; SizeArea_mm2: 1.53; SizeX_mm: 1.7; SizeY_mm: 0.9; SizeZ_mm: 0.75; AEC Category: Q101
D3 D4 = MBR130T1G: Diode, Schottky, 30 V, 1 A, SOD-123; Manufacturer: ON Semiconductor; U/M: EA; Vf_V: 0.47; Value: 30V; Value1: 1A; Value2: 0.47V; Io_A: 1; Vr_V: 30; TJmax_C: 125; RJC_CperW: 108; SizeAreaWB_mm2: 13.095; SizeArea_mm2: 6.545; SizeX_mm: 3.85; SizeY_mm: 1.7; SizeZ_mm: 1.35; AEC Category: Q101
D5 = SML-311UTT86: LED, Red, SMD; Manufacturer: Rohm; Type: AlInGaP; Vf_V: 1.8; Value2: 1.8V; Io_A: 0.002; Value1: W; U/M: EA
D6 = 150060GS75000: LED, Green, SMD; Manufacturer: Wurth Elektronik; Type: InGaN; Vf_V: 3.2; Value2: 3.2V; Io_A: 0.02; Tjmax_C: 85; Value1: W; Angle: 140; U/M: EA
D7 = 150060RS75000: LED, Red, SMD; Manufacturer: Wurth Elektronik; Type: AlInGaP; Vf_V: 2; Value2: 2V; Io_A: 0.03; Vr_V: 5; Tjmax_C: 85; Power_TotalModule: 0.072; Value1: 0.072W; Angle: 140; U/M: EA
J3 J6 = HMTSW-102-07-G-S-240: Header, 100mil, 2x1, Gold, TH; Manufacturer: Samtec; SymbolCreator: a0412235
J7 = 105017-0001: Connector, Receptacle, Micro-USB Type B, R/A, Bottom Mount SMT; Manufacturer: Molex; SymbolCreator: a0412235
J8 = TSW-103-07-G-S: Header, 100mil, 3x1, Gold, TH; Manufacturer: Samtec; SymbolCreator: a0799628; Pitch_mm: 2.54; Gender: Male; Shrouded: N; Row_Count: 1; Current_A: 6.3; Voltage_V: 550; Cert_CSA: Y
L4 L5 = MMZ2012R300A: Ferrite Bead, 30 ohm @ 100 MHz, 1.5 A, 0805; Manufacturer: TDK; Imax_A: 1.5; DCR_ohm: 0.05; Value1: 0.05 ohm; Value2: 1.5A; ZTyp@100MHz_Ohm: 30; SizeAreaWB_mm2: 6.75; SizeArea_mm2: 2.5; SizeX_mm: 2; SizeY_mm: 1.25; SizeZ_mm: 1.45
P1-P4 = SSW-110-23-F-S: Connector, Receptacle, 100mil, 10x1, Gold plated, TH; Manufacturer: Samtec; SymbolCreator: a0411947
Q1-Q3 = BSS138: MOSFET, N-CH, 50 V, 0.22 A, SOT-23; Manufacturer: Fairchild Semiconductor; Alternate Manufacturer: None; U/M: EA; ChType: N; Value: 50V; VdsMax_V: 50; Value1: 6 ohm; Rdson45_ohm: 6; Value2: 1.7 nC; QgTyp_nC: 1.7; Vgs_V: 20; IdsMax_A: 0.22; SizeAreaWB_mm2: 14; SizeArea_mm2: 7.5; SizeX_mm: 2.5; SizeY_mm: 3; SizeZ_mm: 1.1; AEC Category: Q101
R15 = CRCW0402100KFKED: RES, 100 k, 1%, 0.063 W, 0402; Manufacturer: Vishay-Dale; CompType: Resistor; Value: 100k; Res_ohm: 100000; Tolerance_%: 1; Power_W: 0.063; Value2: 0.063W; VDC_V: 50; TempCo: 100 ppm/C; SizeArea_mm2: 0.5; SizeZ_mm: 0.6; EIA_Code: E96; U/M: EA; AEC Category: Q200
R16-R24 R26-R28 R30 R32-R34 = ERJ-2GE0R00X: as R1 on sheet MCU064A_BOOSTXL_CC3135MOD_Engine
R25 R31 = CRCW04021K00JNED: as R7 on sheet MCU064A_BOOSTXL_CC3135MOD_Engine
R29 = ERJ-2GE0R00X: RES, 0, 5%, 0.063 W, 0402; Manufacturer: Panasonic; CompType: Resistor; Value_Code: 0000; Tolerance_%: 5; Power_W: 0.063; Value2: 0.063W; VDC_V: 50; TempCo: 600 ppm/C; EIA_Code: E24; U/M: EA; SizeArea_mm2: 0.5; SizeX_mm: 1; SizeZ_mm: 0.6; AEC Category: Q200
R35 = CRM0805-FX-R100ELF: RES, 0.1, 1%, 0.25 W, 0805; Manufacturer: Bourns; CompType: Resistor; Value: 0.1; Value_Code: R100; Tolerance_%: 1; Power_W: 0.25; Value2: 0.25W; VDC_V: 0; TempCo: 150 ppm/C; EIA_Code: E96; U/M: EA; SizeArea_mm2: 2.5; SizeX_mm: 2; SizeY_mm: 1.25; SizeZ_mm: 1.45; AEC Category: Q200
R36 = CRCW040251K0JNED: RES, 51 k, 5%, 0.063 W, 0402; Manufacturer: Vishay-Dale; CompType: Resistor; Value: 51k; Res_ohm: 51000; Value_Code: 51k0; Tolerance_%: 5; Power_W: 0.063; Value2: 0.063W; VDC_V: 50; TempCo: 200 ppm/C; EIA_Code: E24; U/M: EA; SizeArea_mm2: 0.5; SizeX_mm: 1; SizeZ_mm: 0.6; AEC Category: Q200
R37 = CRCW040230K1FKED: RES, 30.1 k, 1%, 0.063 W, 0402; Manufacturer: Vishay-Dale; CompType: Resistor; Value: 30.1k; Res_ohm: 30100; Value_Code: 30k1; Tolerance_%: 1; Power_W: 0.063; Value2: 0.063W; VDC_V: 50; TempCo: 100 ppm/C; EIA_Code: E96; U/M: EA; SizeArea_mm2: 0.5; SizeZ_mm: 0.6; AEC Category: Q200
R38 = CRCW0402100KJNED: as R3 on sheet MCU064A_BOOSTXL_CC3135MOD_Engine
R39 R48 R49 = ERJ-2RKF1000X: RES, 100, 1%, 0.1 W, 0402; Manufacturer: Panasonic; CompType: Resistor; Value: 100; Value_Code: 100R; Tolerance_%: 1; Power_W: 0.1; Value2: 0.1W; VDC_V: 50; TempCo: 100 ppm/C; EIA_Code: E96; U/M: EA; SizeArea_mm2: 0.5; SizeZ_mm: 0.6; AEC Category: Q200
R40 R42 R44 R45 = RC0603JR-07750RL: RES, 750, 5%, 0.1 W, 0603; Manufacturer: Yageo America; CompType: Resistor; Value: 750; Value_Code: 750R; Tolerance_%: 5; Power_W: 0.1; Value2: 0.1W; VDC_V: 50; TempCo: 100 ppm/C; SizeArea_mm2: 1.28; SizeX_mm: 1.6; SizeY_mm: 0.8; SizeZ_mm: 1; EIA_Code: E24; U/M: EA; AEC Category: Q200
R41 = ERJ-2GE0R00X: RES, 0, 5%, 0.063 W, 0402; Manufacturer: Panasonic; CompType: Resistor; Value: 0; Value_Code: 0000; Tolerance_%: 5; Power_W: 0.063; Value2: 0.063W; VDC_V: 50; TempCo: 600 ppm/C; SizeArea_mm2: 0.5; SizeX_mm: 1; SizeZ_mm: 0.6; EIA_Code: E24; U/M: EA; AEC Category: Q200
R43 R46 R47 = CRCW040210K0JNED: RES, 10 k, 5%, 0.063 W, 0402; Manufacturer: Vishay-Dale; CompType: Resistor; Value: 10k; Res_ohm: 10000; Value_Code: 10k0; Tolerance_%: 5; Power_W: 0.063; Value2: 0.063W; VDC_V: 50; TempCo: 200 ppm/C; EIA_Code: E24; U/M: EA; SizeArea_mm2: 0.5; SizeX_mm: 1; SizeZ_mm: 0.6; AEC Category: Q200
SW1 = EVQ-PSD02K: Switch, Tactile, SPST-NO, SMT; Manufacturer: Panasonic; SymbolCreator: a0799628; VDC_V: 12; SwitchFunction: Off-Mom; PositionCount: 1; CurrentRating_mA: 50
SW2 SW3 = MJTP1117: Switch, SPST-NO, Off-Mom, 1 Pos, 0.05A, 12VDC, TH; Manufacturer: APEM; SymbolCreator: a0799628; VDC_V: 12; PositionCount: 1; CurrentRating_mA: 50
TP1 = 5015: Test Point, Miniature, SMT; Manufacturer: Keystone; CompType: Test Point Loop
U2 = TPS79601DCQR: Ultralow-Noise, High PSRR, Fast, RF, 1-A Low-Dropout Linear Regulators, DCQ0006A (SOT-6); Manufacturer: Texas Instruments; SymbolCreator: Altium; CompType: IC; U/M: EA; SizeArea_mm2: 45.89; SizeAreaWB_mm2: 77.01; SizeX_mm: 7.06; SizeY_mm: 6.5; SizeZ_mm: 1.8

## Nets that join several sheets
GND: MCU064A_BOOSTXL_CC3135MOD_Engine (41 pins), MCU064A_BOOSTXL_CC3135MOD_HostInterface (20 pins)
VBAT_CC: MCU064A_BOOSTXL_CC3135MOD_Engine (5 pins), MCU064A_BOOSTXL_CC3135MOD_HostInterface (C11.1 C12.1 J6.2 R35.2)
VCC_LDO_3V3: MCU064A_BOOSTXL_CC3135MOD_Engine (L3.2), MCU064A_BOOSTXL_CC3135MOD_HostInterface (6 pins)
VCC_MCU_5V: MCU064A_BOOSTXL_CC3135MOD_Engine (R2.1), MCU064A_BOOSTXL_CC3135MOD_HostInterface (D3.2 P3.1)
CC_IRQ: MCU064A_BOOSTXL_CC3135MOD_Engine (R4.1 U1.11), MCU064A_BOOSTXL_CC3135MOD_HostInterface (R18.2)
CC_nHIB: MCU064A_BOOSTXL_CC3135MOD_Engine (U1.4), MCU064A_BOOSTXL_CC3135MOD_HostInterface (R15.1 R25.1 R47.1 SW3.2)
CC_nRESET: MCU064A_BOOSTXL_CC3135MOD_Engine (U1.35), MCU064A_BOOSTXL_CC3135MOD_HostInterface (D2.2 R46.1 SW2.2)
CC_NWP_UART_TX: MCU064A_BOOSTXL_CC3135MOD_Engine (U1.52), MCU064A_BOOSTXL_CC3135MOD_HostInterface (R27.1)
CC_SPI_CLK: MCU064A_BOOSTXL_CC3135MOD_Engine (U1.5), MCU064A_BOOSTXL_CC3135MOD_HostInterface (R29.1)
CC_SPI_CS: MCU064A_BOOSTXL_CC3135MOD_Engine (U1.8), MCU064A_BOOSTXL_CC3135MOD_HostInterface (R19.2)
CC_SPI_DIN: MCU064A_BOOSTXL_CC3135MOD_Engine (U1.6), MCU064A_BOOSTXL_CC3135MOD_HostInterface (R26.2)
CC_SPI_DOUT: MCU064A_BOOSTXL_CC3135MOD_Engine (R3.1 U1.7), MCU064A_BOOSTXL_CC3135MOD_HostInterface (R28.2)
CC_UART1_CTS: MCU064A_BOOSTXL_CC3135MOD_Engine (U1.51), MCU064A_BOOSTXL_CC3135MOD_HostInterface (R21.1)
CC_UART1_RTS: MCU064A_BOOSTXL_CC3135MOD_Engine (R10.1 U1.44), MCU064A_BOOSTXL_CC3135MOD_HostInterface (R23.1)
CC_UART1_RX: MCU064A_BOOSTXL_CC3135MOD_Engine (R6.2 U1.47), MCU064A_BOOSTXL_CC3135MOD_HostInterface (R22.1)
CC_UART1_TX: MCU064A_BOOSTXL_CC3135MOD_Engine (R5.2 U1.46), MCU064A_BOOSTXL_CC3135MOD_HostInterface (R20.1)
CC_WL_UART_TX: MCU064A_BOOSTXL_CC3135MOD_Engine (U1.50), MCU064A_BOOSTXL_CC3135MOD_HostInterface (R30.1)
CC_WLRS232_RX: MCU064A_BOOSTXL_CC3135MOD_Engine (U1.49), MCU064A_BOOSTXL_CC3135MOD_HostInterface (R33.1)
CC_WLRS232_TX: MCU064A_BOOSTXL_CC3135MOD_Engine (U1.48), MCU064A_BOOSTXL_CC3135MOD_HostInterface (R32.1)
MCU_RESET_IN: MCU064A_BOOSTXL_CC3135MOD_Engine (R1.2), MCU064A_BOOSTXL_CC3135MOD_HostInterface (R24.2 R34.2 R41.2)
SOP_00: MCU064A_BOOSTXL_CC3135MOD_Engine (R8.2), MCU064A_BOOSTXL_CC3135MOD_HostInterface (R43.1 SW1.3)
SOP_01: MCU064A_BOOSTXL_CC3135MOD_Engine (R9.2), MCU064A_BOOSTXL_CC3135MOD_HostInterface (R31.1 SW1.4)
TEST_29: MCU064A_BOOSTXL_CC3135MOD_Engine (U1.19), MCU064A_BOOSTXL_CC3135MOD_HostInterface (R16.1)
TEST_30: MCU064A_BOOSTXL_CC3135MOD_Engine (R14.2 U1.21), MCU064A_BOOSTXL_CC3135MOD_HostInterface (R17.1)

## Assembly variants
001: not fitted C4 FID1 FID2 FID3 FID4 FID5 FID6 L3 R3 R4 R5 R6 R8 R9 R10 R11 R12 R13 R14 R16 R17 R32 R33 R34 R35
